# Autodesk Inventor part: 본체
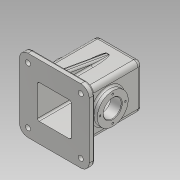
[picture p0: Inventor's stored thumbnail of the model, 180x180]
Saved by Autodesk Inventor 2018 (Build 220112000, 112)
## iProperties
Created: 2022-11
Part Number: 본체
Material: 알루미늄 6061
Document SubType Name: Modeling
Designer: home
Density: 2.7 g/cm^3
Appearance: 알루미늄 - 평지
Mass: 1267.49 g
Surface Area: 1004.35 cm^2
Volume: 469.441 cm^3
Author: home
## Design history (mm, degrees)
sketch "스케치1"
  geometry: L1 (62, -65)-(-62, -65); L2 (-62, -65)-(-62, 65); L3 (-62, 65)-(62, 65); L4 (62, 65)-(62, -65); 3 further points
  constraints: 8 end point, 2 midpoint, 2 parallel, 1 horizontal, 1 horizontal alignment, 1 perpendicular, 1 vertical alignment
  dimensions: "d0" = 124 distance of L1.start L1.end; "d1" = 130 distance of L3.end L1.start
extrude "돌출1" new body sketch "스케치1" distance "d2" = 10; taper "d3" = 0 deg
sketch "스케치2"
  geometry: L1 (-40, 40)-(40, 40); L2 (40, 40)-(40, -40); L3 (40, -40)-(-40, -40); L4 (-40, -40)-(-40, 40); 3 further points
  constraints: 8 end point, 2 midpoint, 2 parallel, 1 horizontal, 1 horizontal alignment, 1 perpendicular, 1 vertical alignment
  dimensions: "d4" = 80 distance of L1.start L1.end; "d5" = 80 distance of L3.end L1.start
extrude "돌출2" join sketch "스케치2" distance "d6" = 107; taper "d7" = 0 deg
sketch "스케치3"
  geometry: L1 (30, -30)-(-30, -30); L2 (-30, -30)-(-30, 30); L3 (-30, 30)-(30, 30); L4 (30, 30)-(30, -30); 3 further points
  constraints: 8 end point, 2 midpoint, 2 parallel, 1 horizontal, 1 horizontal alignment, 1 perpendicular, 1 vertical alignment
  dimensions: "d8" = 60 distance of L1.start L1.end; "d9" = 60 distance of L1.end L2.end
extrude "돌출3" cut sketch "스케치3" distance "d10" = 109; taper "d11" = 0 deg
sketch "스케치4"
  geometry: L1 (105, -10)-(-25, -10) reference; C1 r 27.5 at (40, 45); 2 further points
  constraints: 1 centre point, 1 midpoint, 1 vertical alignment
  dimensions: "d12" = 55 diameter of C1; "d13" = 55 distance from line of L1 C1.centre
extrude "돌출4" join sketch "스케치4" distance "d14" = 9; taper "d15" = 0 deg
sketch "스케치5"
  geometry: C1 r 27.5 at (0, 0) reference; 2 further points
  constraints: 1 coincident
hole "구멍1" sketch "스케치5" at (0, 0) diameter "d16" = 32; stored, may be unused: countersink angle "d20" = 90 deg, drill point angle "d22" = 0 deg; dims "d17" = 6, "d18" = 4, "d19" = 2, "d21" = 32
sketch "스케치6"
  geometry: C1 r 16 at (0, 0) reference; C2 r 27.5 at (0, 0) reference; A1 r 22.5 centre (0, 0) between (0, 22.5) and (-22.5, 0); 3 further points
  constraints: 4 point on circle, 2 horizontal alignment, 2 vertical alignment, 1 centre point, 1 coincident
  dimensions: "d23" = 45 diameter of A1
hole "구멍2" sketch "스케치6" at (0, 22.5), (-22.5, 0), (0, -22.5), (22.5, 0) diameter "d24" = 3.242; stored, may be unused: countersink angle "d28" = 90 deg, drill point angle "d30" = 118 deg; dims "d25" = 8, "d26" = 4, "d27" = 2, "d29" = 10
sketch "스케치7"
  geometry: C1 r 20 at (0, 0); 1 further point
  constraints: 1 centre point, 1 coincident
  dimensions: "d31" = 40 diameter of C1
extrude "돌출5" join sketch "스케치7" distance "d32" = 10; taper "d33" = -10 deg
sketch "스케치8"
  geometry: C1 r 18.237 at (0, 0) reference; 1 further point
  constraints: 1 coincident
hole "구멍3" sketch "스케치8" at (0, 0) diameter "d34" = 21; stored, may be unused: countersink angle "d38" = 90 deg, drill point angle "d40" = 0 deg; dims "d35" = 8, "d36" = 28, "d37" = 4, "d39" = 10
sketch "스케치9"
  geometry: L1 (10, -40)-(117, -40) reference; L2 (95.069, -40)-(10, -55); L3 (10, 65)-(10, -65) reference; L4 (95.069, -40)-(10, -40); L5 (10, -40)-(10, -55); L6 (0, -65)-(10, -65) reference; 1 further point
  constraints: 6 end point, 2 point on line, 1 horizontal, 1 perpendicular
  dimensions: "d41" = 100 deg angle of L2 L3; "d42" = 10 distance from line of L2.end L6
extrude "돌출6" join sketch "스케치9" stored distance "d43" = 10; taper "d44" = 0 deg
fillet "모깎기1" dims "d45" = 8
fillet "모깎기2" dims "d46" = 3
fillet "모깎기3" dims "d47" = 15
fillet "모깎기4" dims "d48" = 3
fillet "모깎기5" dims "d49" = 3
sketch "스케치10"
  geometry: L1 (4.737, -2.252)-(59.263, -2.252); L2 (59.263, -2.252)-(59.263, -11.748); L3 (59.263, -11.748)-(4.737, -11.748); L4 (4.737, -11.748)-(4.737, -2.252); L5 (13.763, 18)-(50.237, 18) reference; L6 (72, -96)-(72, 0) reference; 4 further points
  constraints: 2 midpoint, 1 horizontal alignment, 1 vertical alignment, 2 other
  dimensions: "d51" = 25 distance from line of L5 point (32, -7); "d52" = 40 distance from line of L6 point (32, -7)
feature "엠보싱1" sketch "스케치10" dims "d0" = 124, "d1" = 130, "d53" = 0.5, "d54" = 0
sketch "스케치11"
  geometry: A1 r 15 centre (-47, 50) between (-47, 65) and (-62, 50) reference; A2 r 15 centre (-47, -50) between (-62, -50) and (-47, -65) reference; A3 r 15 centre (47, -50) between (47, -65) and (62, -50) reference; A4 r 15 centre (47, 50) between (62, 50) and (47, 65) reference; 5 further points
  constraints: 4 coincident
hole "구멍4" sketch "스케치11" at (47, 50), (-47, 50), (-47, -50), (47, -50) diameter "d55" = 9; stored, may be unused: countersink angle "d59" = 90 deg, drill point angle "d61" = 0 deg; dims "d56" = 8, "d57" = 28, "d58" = 4, "d60" = 10
chamfer "모따기1" distance "d62" = 1; stored, may be unused: second distance "d63" = 2, angle "d64" = 45 deg
node "솔리드1"
mirror "미러1"
mirror "미러2"
